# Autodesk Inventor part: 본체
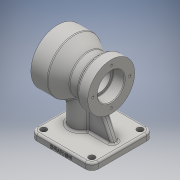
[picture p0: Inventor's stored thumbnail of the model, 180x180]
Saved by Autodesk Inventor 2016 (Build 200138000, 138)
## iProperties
Created: 2019-01
Part Number: 본체
Material: 일반
Document SubType Name: Modeling
Designer: USER
Density: 1 g/cm^3
Appearance: 기본값
Mass: 332.895 g
Surface Area: 600.964 cm^2
Volume: 332.895 cm^3
Author: USER
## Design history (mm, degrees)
sketch "스케치1"
  geometry: L1 (-36, -46)-(36, -46); L2 (46, -36)-(46, 36); L3 (36, 46)-(-36, 46); L4 (-46, 36)-(-46, -36); L5 (-46, -46)-(46, 46); L6 (46, -46)-(-46, 46); C1 r 4.5 at (-36, 36); C2 r 4.5 at (36, 36); C3 r 4.5 at (36, -36); C4 r 4.5 at (-36, -36); A1 r 10 centre (-36, 36) between (-36, 46) and (-46, 36); A2 r 10 centre (36, 36) between (46, 36) and (36, 46); A3 r 10 centre (36, -36) between (36, -46) and (46, -36); A4 r 10 centre (-36, -36) between (-46, -36) and (-36, -46); 1 further point
  constraints: 12 end point, 8 centre point, 8 point on circle, 8 point on line, 8 tangent, 4 coincident, 3 equal radius, 2 midpoint, 2 parallel, 2 perpendicular, 1 horizontal
  dimensions: "d0" = 92 distance of L5.start L6.start; "d1" = 10 radius of A1; "d2" = 9 diameter of C1; "d3" = 9 diameter of C2; "d4" = 9 diameter of C3; "d5" = 9 diameter of C4
extrude "돌출1" new body sketch "스케치1" distance "d6" = 10; taper "d7" = 0 deg
sketch "스케치2"
  geometry: L1 (51, 80)-(-29, 80); L2 (51, 80)-(51, 120); L3 (51, 120)-(26, 120); L4 (26, 120)-(5.215, 108); L5 (5.215, 108)-(-8.126, 108); L6 (-8.126, 108)-(-14, 115); L7 (-14, 115)-(-29, 115); L8 (-29, 115)-(-29, 80); L9 (46, 0)-(46, 10) reference; 1 further point
  constraints: 16 end point, 2 parallel, 2 perpendicular, 1 horizontal, 1 vertical
  dimensions: "d8" = 80 vertical distance of point (0, 0) L1.end; "d9" = 80 diameter of L3 L1; "d10" = 70 diameter of L7 L1; "d11" = 30 deg angle of L5 L4; "d12" = 50 deg angle of L5 L6; "d13" = 56 diameter of L5 L1; "d14" = 80 distance between parallel lines of L8 L2; "d15" = 25 distance of L3.end L2.end; "d16" = 15 distance of L7.end L6.end; "d17" = 5 horizontal distance of L9.start L1.start
revolve "회전1" sketch "스케치2" stored, may be unused: angle "d18" = 90 deg
sketch "스케치3"
  geometry: L1 (-46, 36)-(-46, -36) reference; C1 r 16 at (-16, 0); 1 further point
  constraints: 1 centre point, 1 horizontal alignment
  dimensions: "d19" = 16 radius of C1; "d20" = 30 distance from line of C1.centre L1
extrude "돌출2" join sketch "스케치3" stored distance "d21" = 10; taper "d22" = 0 deg
sketch "스케치4"
  geometry: L1 (0, 10)-(0, 52) reference; L2 (-36, 10)-(36, 10) reference; L3 (-36, 10)-(-46, 10) reference; L4 (-36, 10)-(-25.393, 32.746); L5 (-46, 0)-(-46, 10) reference; 1 further point
  constraints: 2 end point, 1 point on line
  dimensions: "d23" = 25 deg angle of L5 L4; "d24" = 10 distance of L3.end L4.start
feature "리브1" sketch "스케치4" dims "d25" = 1, "d26" = 10, "d27" = 0, "d28" = 0, "d29" = 1, "d30" = 1
sketch "스케치5"
  geometry: L1 (51, 40)-(51, 120) reference; L2 (-29, 45)-(-29, 115) reference; L3 (51, 80)-(-29, 80); L4 (51, 106)-(32, 106); L5 (31, 105)-(31, 96); L6 (31, 96)-(-12, 96); L7 (-14, 45.359)-(-14, 115) reference; L8 (-12, 96)-(-12, 99.4); L9 (-12.6, 100)-(-29, 100); L10 (51, 106)-(51, 80); L11 (-29, 100)-(-29, 80); A1 r 1 centre (32, 105) between (32, 106) and (31, 105); A2 r 0.6 centre (-12.6, 99.4) between (-12, 99.4) and (-12.6, 100); 3 further points
  constraints: 16 end point, 6 perpendicular, 6 point on line, 4 point on circle, 4 tangent, 2 centre point, 2 midpoint, 1 collinear, 1 horizontal
  dimensions: "d31" = 80 vertical distance of point (0, 0) L3.end; "d32" = 52 diameter of L4 L3; "d34" = 40 diameter of L9 L3; "d35" = 20 distance of L4.start point (31, 106); "d36" = 17 distance of point (-12, 100) L9.end; "d37" = 32 diameter of L6 L3; "d38" = 1 radius of A1; "d39" = 0.6 radius of A2
revolve "회전2" sketch "스케치5" stored, may be unused: angle "d40" = 90 deg
sketch "스케치6"
  geometry: C1 r 40 at (0, 0) reference; 2 further points
  constraints: 1 horizontal alignment
  dimensions: "d41" = 33 distance of C1.centre point (33, 0)
hole "구멍1" sketch "스케치6" at (33, 0) diameter "d42" = 3.242; stored, may be unused: countersink angle "d46" = 90 deg, drill point angle "d48" = 118 deg; dims "d43" = 9, "d44" = 4, "d45" = 2, "d47" = 11
sketch "스케치7"
  geometry: C1 r 35 at (0, 0) reference; 2 further points
  constraints: 1 horizontal alignment
  dimensions: "d52" = 27.5 distance of C1.centre point (-27.5, 0)
hole "구멍2" sketch "스케치7" at (-27.5, 0) diameter "d53" = 3.242; stored, may be unused: countersink angle "d57" = 90 deg, drill point angle "d59" = 118 deg; dims "d54" = 9, "d55" = 4, "d56" = 2, "d58" = 11
chamfer "모따기1" distance "d63" = 1; stored, may be unused: second distance "d64" = 2, angle "d65" = 45 deg
fillet "모깎기1" dims "d66" = 3
fillet "모깎기2" dims "d67" = 3
fillet "모깎기3" dims "d68" = 3
sketch "스케치8"
  geometry: L1 (82, 0)-(72, 0) reference; L2 (0, 0)-(-10, 0) reference; 2 further points
  constraints: 1 other
  dimensions: "d69" = 4 vertical distance of L1.start point (36, 4); "d70" = 46 horizontal distance of point (36, 4) L2.end
feature "엠보싱1" sketch "스케치8" dims "d8" = 80, "d9" = 80, "d10" = 70, "d11" = 30 deg, "d12" = 50 deg, "d13" = 56, "d14" = 80, "d15" = 25, "d16" = 15, "d17" = 5, "d71" = 0.5, "d72" = 0
node "솔리드1"
pattern_circular "원형 패턴1" dims angle "d50" = 360 deg
pattern_circular "원형 패턴2" dims angle "d61" = 360 deg
